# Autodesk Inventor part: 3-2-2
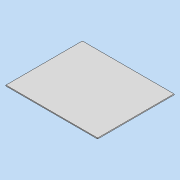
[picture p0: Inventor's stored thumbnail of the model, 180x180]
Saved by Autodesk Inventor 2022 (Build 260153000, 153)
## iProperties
Created: 2021-07
Part Number: 3-2-2
Material: 一般
Document SubType Name: Modeling
Designer: DesignLab
Density: 1 g/cm^3
Appearance: 既定
Author: DesignLab
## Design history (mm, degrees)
sketch "スケッチ1"
  geometry: L1 (150, -125)-(-150, -125); L2 (-150, -125)-(-150, 125); L3 (-150, 125)-(150, 125); L4 (150, 125)-(150, -125); L5 (150, -125)-(-150, 125); L6 (-150, -125)-(150, 125); 1 further point
  constraints: 12 end point, 2 midpoint, 2 parallel, 1 horizontal, 1 perpendicular
  dimensions: "d0" = 300 distance of L2.end L3.end; "d1" = 250 distance of L1.end L2.end
extrude "押し出し1" new body sketch "スケッチ1" distance "d2" = 3; taper "d3" = 0 deg
node "ソリッド1"
